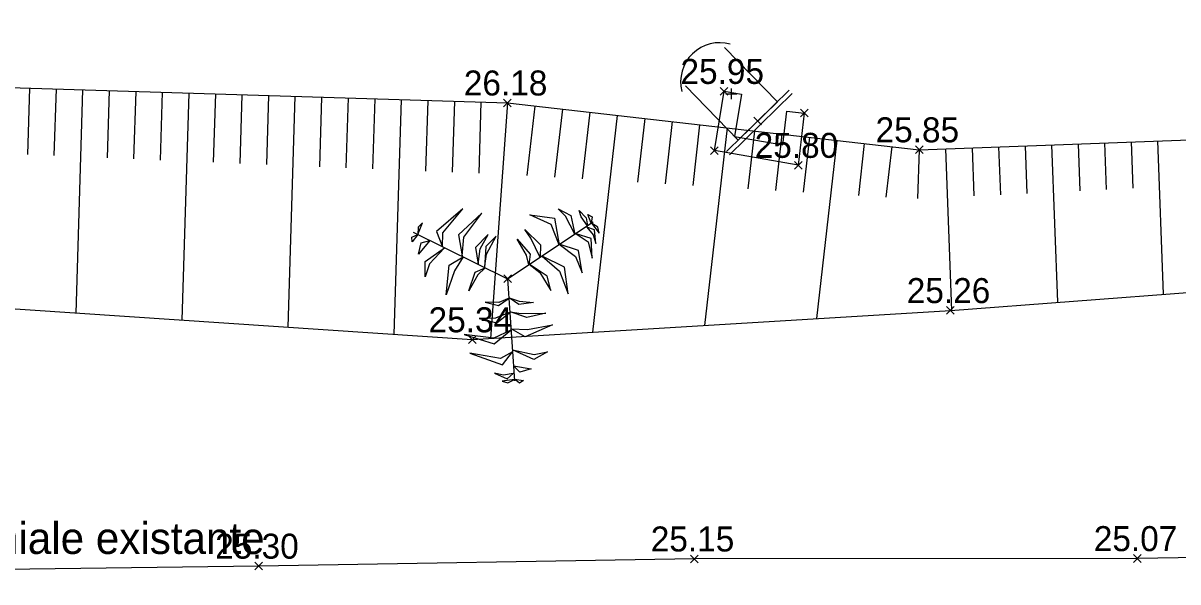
# Model space of a CAD drawing. Extents: x 37864 to 38032, y 453991 to 454052.
# Drawn here: x 37923.89 to 37937.08, y 454001.59 to 454007.96 of the extents above; entities that cross this region are included whole.
import ezdxf

# ---------------------------------------------------------------- set-up
doc = ezdxf.new("R2010")
doc.units = 0
for name, color, linetype in [('DH_CALCUL SURFACE-TEXTE', 7, 'Continuous'), ('DH_HACHURE-MOTIF', 7, 'Continuous'), ('GO_DALLE', 7, 'Continuous'), ('GO_POTEAU', 7, 'Continuous'), ('PS_Const', 7, 'Continuous'), ('PS_Dim', 7, 'Continuous'), ('PS_Hidden', 7, 'Continuous'), ('PS_Solid', 7, 'Continuous')]:
    doc.layers.add(name, color=color, linetype=linetype)

# ---------------------------------------------------------------- blocks, each defined once
blk = doc.blocks.new('CONIFERE')
for p, q in [((-1.078, 0.532), (0, 0)), ((0, 0), (0.976, 0.647)), ((0, 0), (0.08, -1.165))]:
    blk.add_line(p, q)
for points in [[(-0.741, 0.364), (-0.739, 0.523), (-0.511, 0.797), (-0.811, 0.54)], [(0.768, 0.507), (0.663, 0.715), (0.579, 0.797), (0.722, 0.721)], [(-0.519, 0.261), (-0.499, 0.472), (-0.295, 0.746), (-0.559, 0.501)], [(0.588, 0.387), (0.498, 0.618), (0.255, 0.727), (0.538, 0.69)], [(0.913, 0.604), (0.84, 0.707), (0.816, 0.777), (0.899, 0.693)], [(0.956, 0.633), (0.917, 0.732), (0.966, 0.705)], [(-1.025, 0.504), (-0.971, 0.637), (-1.021, 0.589)], [(0.371, 0.242), (0.267, 0.463), (0.197, 0.562), (0.378, 0.385)], [(0.907, 0.587), (0.977, 0.501), (1.009, 0.403), (0.992, 0.558)], [(0.958, 0.634), (1.046, 0.52), (1.029, 0.588)], [(-1.023, 0.503), (-1.089, 0.42), (-1.091, 0.475)], [(-0.888, 0.436), (-1.016, 0.279), (-0.985, 0.411)], [(-0.335, 0.164), (-0.311, 0.342), (-0.22, 0.506), (-0.364, 0.356)], [(-0.262, 0.122), (-0.241, 0.278), (-0.128, 0.485), (-0.248, 0.367)], [(0.245, 0.158), (0.215, 0.27), (0.111, 0.452), (0.259, 0.279)], [(0.782, 0.51), (0.919, 0.422), (0.966, 0.236), (0.956, 0.46)], [(-0.721, 0.354), (-0.891, 0.168), (-0.941, 0.021), (-0.939, 0.198)], [(0.59, 0.394), (0.775, 0.253), (0.851, 0.066), (0.809, 0.322)], [(-0.506, 0.248), (-0.606, 0.089), (-0.702, -0.183), (-0.666, 0.155)], [(0.246, 0.164), (0.37, 0.069), (0.493, -0.134), (0.451, 0.03)], [(0.394, 0.257), (0.593, 0.086), (0.691, -0.173), (0.65, 0.13)], [(-0.256, 0.125), (-0.338, 0.043), (-0.443, -0.139), (-0.368, 0.076)], [(0.018, -0.223), (-0.1, -0.27), (-0.255, -0.267), (-0.103, -0.306)], [(0.018, -0.218), (0.131, -0.256), (0.297, -0.27), (0.128, -0.295)], [(0.029, -0.381), (-0.138, -0.448), (-0.325, -0.452), (-0.124, -0.502)], [(0.029, -0.376), (0.157, -0.398), (0.437, -0.392), (0.22, -0.442)], [(0.041, -0.571), (0.229, -0.578), (0.512, -0.525), (0.202, -0.663)], [(0.037, -0.588), (-0.156, -0.676), (-0.495, -0.637), (-0.152, -0.743)], [(0.058, -0.832), (-0.08, -0.91), (-0.431, -0.849), (-0.059, -0.981)], [(0.057, -0.81), (0.303, -0.864), (0.456, -0.834), (0.301, -0.92)], [(0.069, -0.995), (0.269, -1.028), (0.14, -1.067)], [(0.064, -1.081), (-0.046, -1.098), (-0.147, -1.076), (-0.004, -1.14)], [(0.079, -1.149), (-0.063, -1.168), (0.004, -1.187)], [(0.079, -1.146), (0.184, -1.162), (0.137, -1.191)]]:
    blk.add_lwpolyline(points, close=True)
blk = doc.blocks.new('POINT_DISPLAY')
for p, q in [((-0.04375, -0.04375), (0.04375, 0.04375)), ((-0.04375, 0.04375), (0.04375, -0.04375))]:
    blk.add_line(p, q)
blk = doc.blocks.new('E-VENTOU')
for p, q in [((-0.312, 0.865), (-0.312, 0)), ((0.312, 0.865), (0.312, 0)), ((0.5, 0), (-0.5, 0)), ((-0.312, 0), (0.312, 0)), ((0.5, -0.05), (-0.5, -0.05))]:
    blk.add_line(p, q)
blk.add_arc((0, 0.623), 0.446, 30.0609, 149.9391)
blk.add_blockref('POINT_DISPLAY', (0, 0.432))
blk = doc.blocks.new('POINTCOT')
blk.add_blockref('POINT_DISPLAY', (0, 0))

msp = doc.modelspace()

# ---------------------------------------------------------------- linework, layer by layer
at = {"layer": 'DH_HACHURE-MOTIF'}
for p, q in [((37923.968, 454007.222), (37923.944, 454006.465)), ((37924.271, 454007.213), (37924.247, 454006.453)), ((37924.574, 454007.204), (37924.495, 454004.658)), ((37924.877, 454007.194), (37924.853, 454006.427)), ((37925.18, 454007.185), (37925.156, 454006.415)), ((37925.483, 454007.176), (37925.459, 454006.402)), ((37925.786, 454007.166), (37925.706, 454004.577)), ((37926.089, 454007.157), (37926.065, 454006.377)), ((37926.392, 454007.147), (37926.368, 454006.364)), ((37926.695, 454007.138), (37926.671, 454006.351)), ((37926.998, 454007.129), (37926.917, 454004.496)), ((37927.302, 454007.119), (37927.277, 454006.326)), ((37927.605, 454007.11), (37927.58, 454006.314)), ((37927.908, 454007.101), (37927.883, 454006.301)), ((37928.211, 454007.091), (37928.128, 454004.414)), ((37928.514, 454007.082), (37928.489, 454006.276)), ((37928.817, 454007.073), (37928.792, 454006.263)), ((37929.12, 454007.063), (37929.095, 454006.251)), ((37929.423, 454007.054), (37929.229, 454004.367)), ((37929.736, 454007.018), (37929.646, 454006.227)), ((37930.05, 454006.983), (37929.962, 454006.208)), ((37930.363, 454006.947), (37930.277, 454006.189)), ((37930.676, 454006.911), (37930.395, 454004.438)), ((37930.99, 454006.876), (37930.907, 454006.15)), ((37931.303, 454006.84), (37931.222, 454006.131)), ((37931.616, 454006.805), (37931.538, 454006.112)), ((37931.93, 454006.769), (37931.674, 454004.516)), ((37932.243, 454006.734), (37932.168, 454006.074)), ((37932.556, 454006.698), (37932.483, 454006.055)), ((37932.87, 454006.662), (37932.798, 454006.036)), ((37933.183, 454006.627), (37932.952, 454004.594)), ((37933.496, 454006.591), (37933.429, 454005.998)), ((37933.81, 454006.556), (37933.744, 454005.979)), ((37934.123, 454006.52), (37934.102, 454005.962)), ((37934.425, 454006.531), (37934.493, 454004.688)), ((37934.727, 454006.542), (37934.748, 454005.993)), ((37935.03, 454006.553), (37935.05, 454006.007)), ((37935.332, 454006.564), (37935.352, 454006.022)), ((37935.634, 454006.576), (37935.7, 454004.78)), ((37935.937, 454006.587), (37935.956, 454006.051)), ((37936.239, 454006.598), (37936.259, 454006.066)), ((37936.541, 454006.609), (37936.561, 454006.081)), ((37936.844, 454006.62), (37936.908, 454004.871))]:
    msp.add_line(p, q, dxfattribs=at)
for points in [[(37906.194, 454005.424), (37911.405, 454006.387), (37916.68, 454006.683), (37923.362, 454007.241), (37929.423, 454007.054), (37934.123, 454006.52), (37938.96, 454006.698)], [(37906.194, 454005.424), (37911.469, 454005.161), (37923.405, 454004.731), (37929.021, 454004.355), (37934.479, 454004.687), (37938.691, 454005.007)]]:
    msp.add_lwpolyline(points, dxfattribs=at)
at = {"layer": 'PS_Dim'}
msp.add_lwpolyline([(37941.48, 454001.939), (37936.614, 454001.859), (37931.557, 454001.855), (37926.585, 454001.773), (37921.641, 454001.708), (37916.353, 454001.64), (37911.614, 454001.622), (37906.648, 454001.592), (37904.746, 454001.604)], dxfattribs=at)
at = {"layer": 'PS_Solid'}
msp.add_lwpolyline([(37932.81, 454006.938), (37932.743, 454006.343), (37931.786, 454006.509), (37931.896, 454007.187), (37932.094, 454007.154), (37932.015, 454006.672), (37932.568, 454006.576), (37932.611, 454006.96), (37932.81, 454006.938)], dxfattribs=at)

# ---------------------------------------------------------------- block references
at = {"layer": 'DH_CALCUL SURFACE-TEXTE', "rotation": 2.2526485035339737e-05}
for p in [(37931.896, 454007.187), (37929.423, 454007.054), (37932.81, 454006.938), (37932.281, 454006.848), (37931.786, 454006.509), (37934.123, 454006.52), (37932.743, 454006.343), (37929.424, 454005.049), (37934.479, 454004.687), (37929.021, 454004.355), (37936.614, 454001.859), (37926.585, 454001.773), (37931.557, 454001.855)]:
    msp.add_blockref('POINTCOT', p, dxfattribs=at)
at = {"layer": 'GO_DALLE', "rotation": 44.273362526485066}
msp.add_blockref('E-VENTOU', (37932.281, 454006.848), dxfattribs=at)
at = {"layer": 'PS_Const', "rotation": 2.2526485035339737e-05}
msp.add_blockref('CONIFERE', (37929.424, 454005.049), dxfattribs=at)

# ---------------------------------------------------------------- texts
at = {"layer": 'GO_POTEAU'}
for s, p in [('25.95', (37931.398, 454007.27)), ('26.18', (37928.925, 454007.138)), ('25.85', (37933.625, 454006.604)), ('25.80', (37932.245, 454006.427)), ('25.26', (37933.981, 454004.771)), ('25.34', (37928.523, 454004.438)), ('25.15', (37931.059, 454001.939)), ('25.07', (37936.116, 454001.943)), ('25.30', (37926.087, 454001.857))]:
    msp.add_text(s, height=0.285, rotation=0, dxfattribs=at).set_placement(p)
at = {"layer": 'PS_Hidden'}
msp.add_text('Cloture domaniale existante', height=0.36, rotation=360, dxfattribs=at).set_placement((37920.684, 454001.911))

doc.saveas('drawing.dxf')
